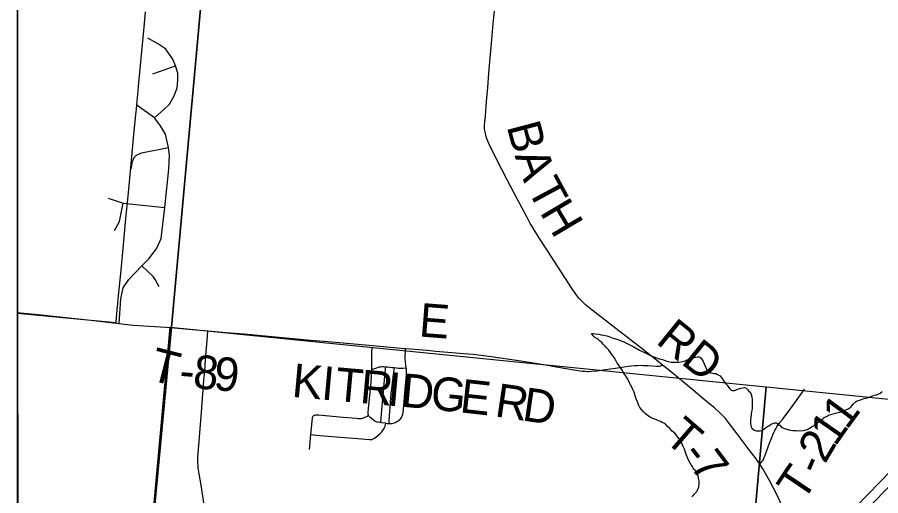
# Model space of a CAD drawing. Extents: x -1.4 to 35.4, y 0 to 22.
# Drawn here: x 24.49 to 25.952, y 17.676 to 18.486 of the extents above; entities that cross this region are included whole.
import ezdxf

# ---------------------------------------------------------------- set-up
doc = ezdxf.new("R2010")
doc.units = 0
for name, color, linetype in [('GM_X_City_Street', 7, 'Continuous'), ('GM_X_County_Text', 7, 'Continuous'), ('GM_X_Minor_River', 7, 'Continuous'), ('GM_X_Section', 7, 'Continuous'), ('GM_X_State_Route', 7, 'Continuous'), ('GM_X_Township_Road', 7, 'Continuous'), ('GM_X_Township_Road_Text', 7, 'Continuous'), ('SC_Scratch1', 7, 'Continuous'), ('SH_Border', 7, 'Continuous'), ('SH_Cut_Line', 7, 'Continuous')]:
    doc.layers.add(name, color=color, linetype=linetype)

msp = doc.modelspace()

# ---------------------------------------------------------------- linework, layer by layer
at = {"layer": 'GM_X_City_Street'}
for p, q in [((24.7194, 18.3897), (24.7576, 18.4033)), ((24.4897, 17.8962), (24.4901, 17.8962))]:
    msp.add_line(p, q, dxfattribs=at)
for points in [[(24.7221, 18.3153), (24.7392, 18.3306), (24.7473, 18.3388), (24.7555, 18.3528), (24.7603, 18.3664), (24.7614, 18.3794), (24.7614, 18.3913), (24.7576, 18.4033), (24.7533, 18.4147), (24.7408, 18.432), (24.7273, 18.4412), (24.711, 18.4504)], [(24.662, 17.9672), (24.6652, 18.0092), (24.6692, 18.0275), (24.6784, 18.0417), (24.7007, 18.0651), (24.7129, 18.0773), (24.7262, 18.0946), (24.7333, 18.1109), (24.7394, 18.1638), (24.7465, 18.2288), (24.7475, 18.2522), (24.7455, 18.2654), (24.7404, 18.2878), (24.7323, 18.302), (24.7221, 18.3153), (24.6926, 18.3366)], [(24.6827, 18.2283), (24.6847, 18.2418), (24.6878, 18.2481), (24.6918, 18.2525), (24.7, 18.2563), (24.7455, 18.2654)], [(24.6438, 18.1795), (24.6692, 18.1709), (24.7394, 18.1638)], [(24.6545, 18.1246), (24.6626, 18.1399), (24.6692, 18.1709)], [(24.7297, 18.0293), (24.7231, 18.0415), (24.7196, 18.0466), (24.7007, 18.0651)], [(24.4897, 17.986), (24.5249, 17.9825), (24.6193, 17.9724), (24.662, 17.9672), (24.6855, 17.9644), (24.751, 17.9604)]]:
    msp.add_lwpolyline(points, dxfattribs=at)
at = {"layer": 'GM_X_County_Text'}
msp.add_lwpolyline([(24.4897, 18.6045), (24.4897, 17.9845), (24.5547, 17.9785), (24.5604, 17.978), (24.657, 17.969), (24.6578, 17.9772), (24.6613, 18.0141), (24.6654, 18.0574), (24.6695, 18.1006), (24.6737, 18.1449), (24.6779, 18.1885), (24.6819, 18.2314), (24.6867, 18.2812), (24.6905, 18.3212), (24.6913, 18.33), (24.6921, 18.3383), (24.6942, 18.3606), (24.6949, 18.3685), (24.6983, 18.4042), (24.6995, 18.416), (24.704, 18.4635), (24.7045, 18.4692), (24.707, 18.4951)], dxfattribs=at)
at = {"layer": 'GM_X_Minor_River'}
for points in [[(25.6318, 17.6736), (25.6338, 17.6758), (25.6357, 17.6781), (25.6376, 17.6803), (25.64, 17.683), (25.6411, 17.6852), (25.6423, 17.6879), (25.6435, 17.6901), (25.6439, 17.692), (25.6443, 17.6939), (25.6444, 17.6962), (25.6444, 17.6985), (25.644, 17.7008), (25.6437, 17.703), (25.643, 17.7057), (25.6423, 17.7092), (25.6412, 17.7122), (25.6397, 17.7145), (25.6386, 17.7168), (25.6375, 17.7187), (25.6356, 17.7203), (25.6341, 17.7226), (25.6327, 17.7249), (25.6304, 17.728), (25.6282, 17.7318), (25.626, 17.736), (25.6238, 17.7414), (25.6209, 17.749), (25.6191, 17.7544), (25.6173, 17.759), (25.6158, 17.7621), (25.6151, 17.7647), (25.614, 17.7666), (25.6125, 17.7686), (25.6114, 17.7705), (25.6036, 17.7809), (25.5987, 17.7851), (25.5946, 17.7894), (25.5908, 17.7929), (25.5875, 17.796), (25.5845, 17.7983), (25.5815, 17.7999), (25.5788, 17.8014), (25.5758, 17.8026), (25.5728, 17.8038), (25.5694, 17.8054), (25.566, 17.8066), (25.5615, 17.8089), (25.5585, 17.8105), (25.5555, 17.8125), (25.5529, 17.8148), (25.5499, 17.8175), (25.5469, 17.821), (25.5439, 17.8248), (25.5417, 17.8294), (25.5395, 17.8344), (25.5377, 17.8398), (25.5359, 17.8447), (25.5341, 17.8508), (25.5319, 17.8554), (25.53, 17.8596), (25.5282, 17.8635), (25.5264, 17.8669), (25.5245, 17.8708), (25.5223, 17.8746), (25.5197, 17.8792), (25.5167, 17.8834), (25.5142, 17.8877), (25.5119, 17.8911), (25.5093, 17.895), (25.5056, 17.9003), (25.503, 17.9049), (25.5001, 17.9096), (25.4971, 17.9142), (25.4941, 17.9184), (25.4912, 17.9222), (25.4882, 17.925), (25.4859, 17.9273), (25.4845, 17.9296), (25.4822, 17.9315), (25.4789, 17.9358), (25.4755, 17.9377), (25.4732, 17.94), (25.471, 17.9416), (25.4668, 17.9443), (25.4642, 17.9474), (25.462, 17.9505), (25.4643, 17.9504)], [(25.4643, 17.9504), (25.4684, 17.9496), (25.4741, 17.9491), (25.4783, 17.9483), (25.4828, 17.9475), (25.4878, 17.9463), (25.493, 17.9446), (25.4987, 17.9426), (25.5047, 17.9406), (25.5112, 17.9386), (25.518, 17.9359), (25.5255, 17.9319), (25.5334, 17.9276), (25.5432, 17.9221), (25.5503, 17.9186), (25.5571, 17.9155), (25.5628, 17.9127), (25.5677, 17.9107), (25.5722, 17.9091), (25.5763, 17.9075), (25.5801, 17.9067), (25.5839, 17.9059), (25.5877, 17.9043), (25.5918, 17.9031), (25.5968, 17.9019), (25.6043, 17.9018), (25.61, 17.902), (25.6158, 17.9027), (25.6203, 17.9041), (25.6238, 17.9056), (25.6268, 17.9071), (25.6303, 17.9082), (25.6333, 17.9093), (25.6356, 17.9096), (25.6413, 17.911), (25.6443, 17.9106), (25.6462, 17.9098), (25.6492, 17.906), (25.6511, 17.9029), (25.6529, 17.899), (25.6543, 17.8948), (25.6562, 17.891), (25.6576, 17.8876), (25.6595, 17.8853), (25.6621, 17.8841), (25.664, 17.8837), (25.6667, 17.8832), (25.6693, 17.8828), (25.6724, 17.8824), (25.6754, 17.8812), (25.6773, 17.88), (25.6795, 17.8788), (25.681, 17.8769), (25.6829, 17.8742), (25.6851, 17.8711), (25.6884, 17.8665), (25.6914, 17.8627), (25.6936, 17.8596), (25.6959, 17.8565), (25.6985, 17.8546), (25.7004, 17.8538), (25.7038, 17.8541), (25.7057, 17.8545), (25.708, 17.8556), (25.7114, 17.8566), (25.7149, 17.8577), (25.7183, 17.8584), (25.721, 17.8588), (25.7236, 17.858), (25.7258, 17.8553), (25.7277, 17.8533), (25.7311, 17.8502), (25.7322, 17.8468), (25.7332, 17.843), (25.7339, 17.8384), (25.7342, 17.8338), (25.7337, 17.8228), (25.7328, 17.8183), (25.732, 17.8134), (25.7316, 17.8084), (25.7311, 17.8039), (25.731, 17.7982), (25.7317, 17.7947), (25.7324, 17.7921), (25.7332, 17.7901), (25.7365, 17.7874), (25.7388, 17.7863), (25.7414, 17.7854), (25.7445, 17.7854), (25.7475, 17.7857), (25.7502, 17.7861), (25.7536, 17.7879), (25.7559, 17.7901), (25.759, 17.7924), (25.7621, 17.7942), (25.7648, 17.7961), (25.7674, 17.7976), (25.7705, 17.7987), (25.7724, 17.799), (25.7743, 17.799), (25.7766, 17.7982)], [(25.7766, 17.7982), (25.7788, 17.7962), (25.7814, 17.7943), (25.7829, 17.7924), (25.7848, 17.7912), (25.7871, 17.79), (25.792, 17.7884), (25.798, 17.7868), (25.8029, 17.786), (25.8056, 17.7859), (25.8079, 17.7859), (25.8109, 17.7858), (25.814, 17.7861), (25.817, 17.7857), (25.8204, 17.786), (25.8231, 17.7864), (25.8269, 17.7878), (25.8296, 17.7893), (25.8319, 17.7904), (25.8346, 17.7923), (25.8376, 17.7941), (25.8411, 17.7967), (25.8445, 17.7986), (25.8472, 17.8012), (25.8503, 17.8038), (25.8534, 17.8056), (25.8561, 17.8079), (25.8595, 17.8101), (25.8633, 17.8119), (25.8672, 17.8134), (25.871, 17.8145), (25.8752, 17.8155), (25.8794, 17.8166), (25.8851, 17.818), (25.8889, 17.8195), (25.8927, 17.821), (25.8965, 17.8228), (25.8992, 17.8243), (25.9011, 17.8258), (25.9027, 17.8276), (25.905, 17.8306), (25.9081, 17.834), (25.9119, 17.8362), (25.9158, 17.8377), (25.9188, 17.8388), (25.9219, 17.8395), (25.9238, 17.8402), (25.9261, 17.8406), (25.9287, 17.8417), (25.9383, 17.8449), (25.9413, 17.846), (25.9444, 17.8467), (25.9467, 17.8474), (25.9501, 17.8489), (25.9539, 17.8523)]]:
    msp.add_lwpolyline(points, dxfattribs=at)
at = {"layer": 'GM_X_Section'}
msp.add_lwpolyline([(25.7575, 17.8601), (25.6685, 16.8528), (24.6573, 16.9582), (24.7488, 17.9613)], close=True, dxfattribs=at)
msp.add_lwpolyline([(26.7252, 17.5166), (26.6457, 16.7545), (25.6685, 16.8528), (25.7575, 17.8601), (26.5998, 17.7755)], dxfattribs=at)
at = {"layer": 'GM_X_State_Route'}
for points in [[(25.9103, 17.6582), (25.9694, 17.7186)], [(25.9239, 17.6483), (25.9931, 17.7197)]]:
    msp.add_lwpolyline(points, dxfattribs=at)
at = {"layer": 'GM_X_Township_Road'}
msp.add_line((24.9844, 17.7538), (24.9867, 17.7791), dxfattribs=at)
for points in [[(25.4607, 17.9917), (25.4575, 17.9942), (25.4519, 17.9988), (25.4459, 18.0043), (25.4405, 18.0104), (25.4355, 18.0168), (25.4282, 18.0276), (25.3882, 18.0895), (25.3752, 18.1093), (25.3664, 18.1232), (25.3606, 18.1325), (25.3581, 18.1367), (25.3527, 18.1465), (25.336, 18.1785), (25.3193, 18.2104), (25.2997, 18.2478), (25.2878, 18.2721), (25.2861, 18.2758), (25.285, 18.279), (25.2841, 18.2818), (25.2828, 18.2867), (25.2819, 18.291), (25.2814, 18.2942), (25.281, 18.2974), (25.2809, 18.3011), (25.2809, 18.3035), (25.2812, 18.3079), (25.2822, 18.3184), (25.2844, 18.3431), (25.2861, 18.3666), (25.2882, 18.3908), (25.2906, 18.4168), (25.2921, 18.4347), (25.2956, 18.4749), (25.2976, 18.496)], [(25.5822, 17.8969), (25.5718, 17.9053), (25.5402, 17.93), (25.4908, 17.9683), (25.4777, 17.9784), (25.4607, 17.9917)], [(24.751, 17.9604), (24.7551, 17.9601), (24.7922, 17.9568), (24.8122, 17.955)], [(24.8097, 17.6378), (24.8008, 17.6937), (24.7977, 17.7128), (24.7962, 17.7231), (24.7958, 17.7269), (24.7955, 17.7323), (24.7955, 17.7367), (24.7956, 17.7416), (24.7964, 17.7539), (24.8014, 17.8173), (24.805, 17.863), (24.8057, 17.8716), (24.807, 17.8864), (24.8086, 17.9066), (24.8115, 17.9455), (24.8122, 17.955)], [(24.8122, 17.955), (24.8436, 17.9522), (24.8739, 17.9495), (24.945, 17.9429), (24.9864, 17.939), (25.0093, 17.9371), (25.0916, 17.9298), (25.1454, 17.9251), (25.1474, 17.925)], [(25.09, 17.8898), (25.0902, 17.9191), (25.0905, 17.9255)], [(25.1481, 17.892), (25.1475, 17.896), (25.1468, 17.9028), (25.1466, 17.9061), (25.1466, 17.91), (25.1466, 17.9131), (25.1468, 17.9169), (25.1472, 17.9226), (25.1474, 17.925)], [(25.1474, 17.925), (25.1837, 17.9219), (25.1985, 17.9206), (25.2455, 17.9167), (25.2615, 17.9151), (25.275, 17.9135), (25.2959, 17.9107), (25.335, 17.9052), (25.3844, 17.8974), (25.4029, 17.8941), (25.4354, 17.8881), (25.4465, 17.8866), (25.4506, 17.8863), (25.4546, 17.8862), (25.458, 17.8861), (25.4621, 17.8863), (25.4715, 17.8873), (25.4856, 17.8894), (25.5027, 17.8918), (25.5242, 17.8951), (25.5289, 17.8956), (25.5349, 17.8961), (25.5398, 17.8964), (25.5449, 17.8965), (25.5494, 17.8964), (25.5571, 17.8959), (25.5725, 17.8949), (25.5758, 17.895), (25.5773, 17.8951), (25.5787, 17.8955), (25.5805, 17.896), (25.5822, 17.8969)], [(25.09, 17.8898), (25.0918, 17.8901), (25.0944, 17.8908), (25.0966, 17.8916), (25.0994, 17.8928), (25.1029, 17.8937), (25.1048, 17.8941), (25.1071, 17.8944), (25.1098, 17.8943), (25.1133, 17.8939)], [(25.1051, 17.7994), (25.1057, 17.8068), (25.1072, 17.8268), (25.1119, 17.8781), (25.113, 17.8899), (25.1133, 17.8939)], [(25.1133, 17.8939), (25.1166, 17.8937), (25.1246, 17.8929), (25.1281, 17.8926)], [(25.7468, 17.7293), (25.7405, 17.7381), (25.7289, 17.7534), (25.7236, 17.7603), (25.7169, 17.7693), (25.7083, 17.7807), (25.6936, 17.7999), (25.6886, 17.8062), (25.6836, 17.8117), (25.6797, 17.8156), (25.6701, 17.8243), (25.6625, 17.8307), (25.6529, 17.8386), (25.6338, 17.8542), (25.5915, 17.8894), (25.5822, 17.8969)], [(25.0844, 17.8118), (25.0841, 17.8129), (25.084, 17.8136), (25.0839, 17.8152), (25.0839, 17.8171), (25.084, 17.819), (25.0841, 17.821), (25.0843, 17.8233), (25.0887, 17.8676), (25.0895, 17.8787), (25.09, 17.8898)], [(25.1192, 17.7981), (25.1196, 17.8032), (25.1221, 17.8414), (25.1229, 17.8496), (25.1237, 17.8569), (25.126, 17.8757), (25.1273, 17.8852), (25.1277, 17.8885), (25.1281, 17.8926)], [(25.1192, 17.7981), (25.1214, 17.798), (25.123, 17.798), (25.1243, 17.7982), (25.1259, 17.7985), (25.1279, 17.7991), (25.1294, 17.7997), (25.1313, 17.8006), (25.133, 17.8015), (25.1345, 17.8026), (25.1378, 17.8054), (25.1391, 17.8067), (25.14, 17.808), (25.1409, 17.8094), (25.1416, 17.811), (25.1423, 17.8128), (25.1427, 17.8146), (25.143, 17.8167), (25.1446, 17.8344), (25.1459, 17.8499), (25.1486, 17.8806), (25.1488, 17.8836), (25.1486, 17.8867), (25.1484, 17.8903), (25.1481, 17.892)], [(25.1281, 17.8926), (25.1352, 17.8918), (25.1385, 17.8916), (25.1426, 17.8915), (25.1481, 17.892)], [(25.7468, 17.7293), (25.7488, 17.7313), (25.7505, 17.7334), (25.7516, 17.735), (25.7524, 17.7361), (25.7529, 17.7375), (25.7558, 17.7445), (25.7585, 17.752), (25.763, 17.7645), (25.7659, 17.7717), (25.7689, 17.779), (25.7707, 17.783), (25.7722, 17.7859), (25.7738, 17.7889), (25.7757, 17.7921), (25.7782, 17.7957), (25.7809, 17.7995), (25.785, 17.8049), (25.8015, 17.8268), (25.8063, 17.8331), (25.8228, 17.8559)], [(24.9867, 17.7791), (24.9893, 17.8069), (24.9895, 17.8081), (24.9897, 17.8087), (24.9902, 17.8098), (24.9907, 17.8105), (24.9912, 17.811)], [(24.9912, 17.811), (24.9924, 17.8118), (24.9934, 17.8122), (24.995, 17.8125), (24.9959, 17.8126), (24.9969, 17.8126), (24.9982, 17.8126), (24.9997, 17.8125), (25.0416, 17.8086), (25.0638, 17.8068), (25.0663, 17.8066), (25.0705, 17.8065), (25.0716, 17.8065), (25.0722, 17.8065), (25.0747, 17.8072), (25.0819, 17.8106), (25.0844, 17.8118)], [(25.1051, 17.7994), (25.1035, 17.7996), (25.1003, 17.8), (25.0988, 17.8003), (25.0972, 17.8007), (25.0958, 17.8014), (25.0929, 17.8035), (25.0892, 17.8064), (25.087, 17.8084), (25.0857, 17.8098), (25.0848, 17.8111), (25.0844, 17.8118)], [(24.9867, 17.7791), (24.996, 17.7784), (25.0294, 17.7756), (25.0665, 17.7723), (25.0863, 17.7708), (25.0876, 17.7708), (25.0882, 17.7708), (25.0899, 17.7711), (25.0912, 17.7715), (25.0923, 17.772), (25.0934, 17.7725), (25.0945, 17.7732), (25.0998, 17.7772), (25.1041, 17.7809), (25.1071, 17.784), (25.1083, 17.7856), (25.1093, 17.787), (25.1107, 17.7894), (25.1114, 17.7908), (25.1119, 17.7924), (25.1124, 17.7937), (25.1129, 17.7956), (25.1135, 17.7984)], [(25.1135, 17.7984), (25.1069, 17.7992), (25.1051, 17.7994)], [(25.1135, 17.7984), (25.1161, 17.7982), (25.1181, 17.7981), (25.1192, 17.7981)], [(25.8075, 17.5661), (25.8069, 17.5675), (25.8058, 17.5705), (25.8052, 17.5729), (25.8044, 17.5759), (25.8004, 17.5915), (25.7956, 17.6128), (25.7909, 17.634), (25.7888, 17.6427), (25.7873, 17.6484), (25.7859, 17.6529), (25.7844, 17.6572), (25.7831, 17.6609), (25.7813, 17.6652), (25.776, 17.6764), (25.7631, 17.7012), (25.7518, 17.7212), (25.7492, 17.7255), (25.7468, 17.7293)]]:
    msp.add_lwpolyline(points, dxfattribs=at)
at = {"layer": 'SC_Scratch1'}
for points in [[(26.9481, 19.8546), (24.4897, 19.8546), (24.4897, 14.8759)], [(24.8423, 18.9651), (24.7507, 17.961), (24.7137, 17.5642), (24.6906, 17.3173), (24.6565, 16.9596), (24.6233, 16.6059), (24.6203, 16.5765), (24.5837, 16.1806)], [(24.5837, 16.1806), (24.6203, 16.5765), (24.6233, 16.6059), (24.6565, 16.9596), (24.6906, 17.3173), (24.7137, 17.5642), (24.7507, 17.961), (24.8423, 18.9651)]]:
    msp.add_lwpolyline(points, dxfattribs=at)
at = {"layer": 'SH_Border'}
msp.add_lwpolyline([(24.4897, 19.8546), (24.4921, 13.0546), (31.2897, 13.0546), (31.2897, 19.8546)], close=True, dxfattribs=at)
at = {"layer": 'SH_Cut_Line'}
for points in [[(26.9481, 19.8546), (24.4897, 19.8546), (24.4897, 14.8759)], [(24.5837, 16.1806), (24.6203, 16.5765), (24.6233, 16.6059), (24.6565, 16.9596), (24.6906, 17.3173), (24.7137, 17.5642), (24.7507, 17.961), (24.8423, 18.9651)], [(24.8423, 18.9651), (24.7507, 17.961), (24.7137, 17.5642), (24.6906, 17.3173), (24.6565, 16.9596), (24.6233, 16.6059), (24.6203, 16.5765), (24.5837, 16.1806)]]:
    msp.add_lwpolyline(points, dxfattribs=at)

# ---------------------------------------------------------------- texts
at = {"layer": 'GM_X_Township_Road_Text'}
for s, height, rotation, p in [('B', 0.0568, 284.8305, (25.3181, 18.3013)), ('A', 0.0568, 289.3673, (25.3315, 18.2515)), ('T', 0.0568, 298.3776, (25.352, 18.1954)), ('H', 0.0568, 300.6701, (25.3734, 18.1558)), ('E', 0.0568, 355.5222, (25.1687, 17.9455)), ('RD', 0.05682, 320.953, (25.5691, 17.9351)), ('T', 0.0568, 345.5636, (24.711, 17.8723)), ('8', 0.0568, 354.7733, (24.7859, 17.8582)), ('9', 0.0568, 354.9093, (24.8209, 17.855)), ('K', 0.0568, 354.8202, (24.9533, 17.8433)), ('I', 0.0568, 354.8249, (25.0031, 17.8388)), ('-', 0.0568, 355.5431, (24.7628, 17.86)), ('T', 0.0568, 354.8201, (25.0263, 17.8367)), ('R', 0.0568, 354.8176, (25.0686, 17.8329)), ('I', 0.0568, 354.8098, (25.1151, 17.8287)), ('D', 0.0568, 354.7398, (25.1383, 17.8266)), ('G', 0.0568, 354.3445, (25.188, 17.822)), ('E', 0.0568, 353.6529, (25.2376, 17.8171)), ('R', 0.0568, 351.5823, (25.2966, 17.8102)), ('D', 0.0568, 351.7301, (25.343, 17.8033)), ('1', 0.0568, 53.714, (25.8942, 17.7859)), ('T', 0.0568, 319.0473, (25.5827, 17.7702)), ('1', 0.0568, 55.1256, (25.8744, 17.7575)), ('2', 0.0568, 59.4802, (25.8572, 17.7283)), ('-', 0.0568, 308.0424, (25.6128, 17.7444)), ('7', 0.0568, 306.9219, (25.627, 17.7262)), ('-', 0.0568, 66.5081, (25.8487, 17.7085)), ('T', 0.0568, 56.0395, (25.8196, 17.6633))]:
    msp.add_text(s, height=height, rotation=rotation, dxfattribs=at).set_placement(p)

doc.saveas('drawing.dxf')
